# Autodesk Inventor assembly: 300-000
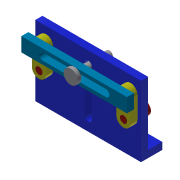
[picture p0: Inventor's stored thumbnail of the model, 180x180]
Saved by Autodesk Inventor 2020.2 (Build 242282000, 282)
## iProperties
Created: 2014-01
Part Number: 300-000
Document SubType Name: Assembly
Designer: F.Stasiak
Manager: www.cadconsulting.pl
Company: Fabian Stasiak CAD Consulting
Author: F.Stasiak
Subject: Zbiór ćwiczeń. Autodesk Inventor 2020. Kurs podstawowy
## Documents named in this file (6)
- C:\2020_Kurs_podstawowy\R6 Zespoły\Warsztat\Gotowe\300-000_Gotowy_W.iam
- C:\2020_Kurs_podstawowy\R6 Zespoły\Warsztat\Komponenty\300-001.ipt
- C:\2020_Kurs_podstawowy\R6 Zespoły\Warsztat\Komponenty\300-002.ipt
- C:\2020_Kurs_podstawowy\R6 Zespoły\Warsztat\Komponenty\300-003.ipt
- C:\2020_Kurs_podstawowy\R6 Zespoły\Warsztat\Komponenty\300-004.ipt
- C:\2020_Kurs_podstawowy\R6 Zespoły\Warsztat\Komponenty\300-005.ipt
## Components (7 placed, 5 different names)
1. 300-001:1 — Wstaw:1, Wstaw:2, Wstaw:5, Wstaw:6
2. 300-002:1 — NAPĘD, Wstaw:1, Wstaw:3
3. 300-002:2 — Wstaw:2, Wstaw:4
4. 300-003:1 — Wstaw:3, Wstaw:4, Zestawiający:1
5. 300-004:1 — Wstaw:6
6. 300-004:2 — Wstaw:5
7. 300-005:1 — Zestawiający:1
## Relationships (8: Insert 6, Angle 1, Mate 1)
- NAPĘD [Angle]: 300-002:1
- Wstaw:1 [Insert]: 300-001:1 ↔ 300-002:1
- Wstaw:2 [Insert]: 300-001:1 ↔ 300-002:2
- Wstaw:3 [Insert]: 300-002:1 ↔ 300-003:1
- Wstaw:4 [Insert]: 300-002:2 ↔ 300-003:1
- Wstaw:5 [Insert]: 300-001:1 ↔ 300-004:2
- Wstaw:6 [Insert]: 300-001:1 ↔ 300-004:1
- Zestawiający:1 [Mate]: 300-003:1 ↔ 300-005:1
